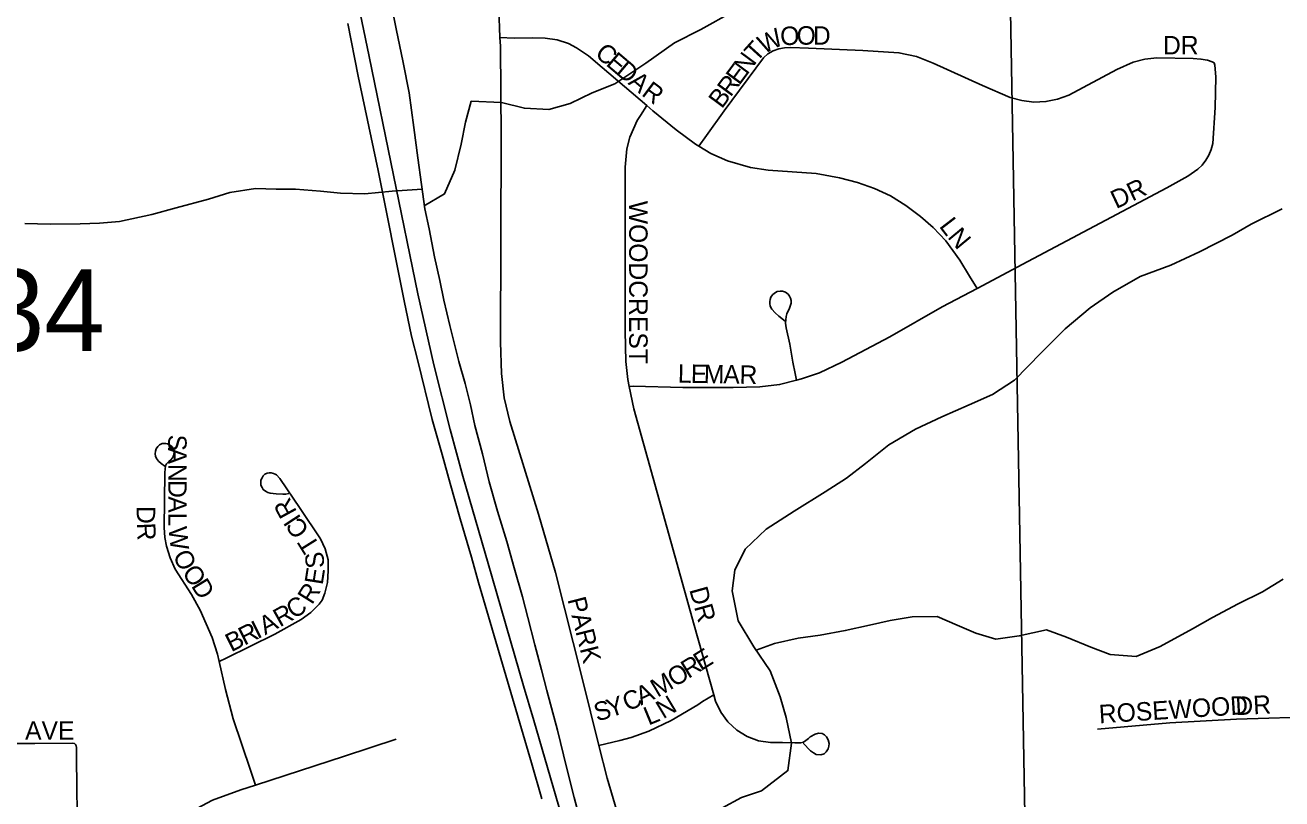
# Model space of a CAD drawing. Extents: x 1985906 to 2360102, y 891258 to 1222054.
# Drawn here: x 2127638 to 2131045, y 1027049 to 1029146 of the extents above; entities that cross this region are included whole.
import ezdxf

# ---------------------------------------------------------------- set-up
doc = ezdxf.new("R2010")
doc.units = 0
for name, color, linetype in [('GM_X_City_Street', 7, 'Continuous'), ('GM_X_City_Street_Text', 7, 'Continuous'), ('GM_X_Minor_River', 7, 'Continuous'), ('GM_X_Section', 7, 'Continuous'), ('GM_X_Section_Text', 7, 'Continuous'), ('GM_X_State_Route', 7, 'Continuous')]:
    doc.layers.add(name, color=color, linetype=linetype)

msp = doc.modelspace()

# ---------------------------------------------------------------- linework, layer by layer
at = {"layer": 'GM_X_City_Street'}
for points in [[(2128925.4, 1029111.7), (2128919.2, 1029268.5), (2128910.3, 1029349.7), (2128894.7, 1029429.9), (2128872.7, 1029508.6), (2128822.4, 1029647.2), (2128746.9, 1029846.9), (2128710.7, 1029956.1), (2128670.5, 1030098.5), (2128656.9, 1030147)], [(2128925.4, 1029111.7), (2128963.4, 1029110.6), (2129013.5, 1029111.3), (2129048.2, 1029110), (2129080.2, 1029106.2), (2129111, 1029095.7), (2129133.1, 1029084.2), (2129165.5, 1029062.7), (2129202.6, 1029030.6), (2129323.1, 1028927.7)], [(2129193.5, 1027193.3), (2129147.7, 1027376.3), (2129076, 1027662.8), (2129029.8, 1027820.2), (2128951.7, 1028071.3), (2128937, 1028135.7), (2128929.5, 1028201.4), (2128927, 1028286.4), (2128928.4, 1028842.4), (2128926.4, 1029088.5), (2128925.4, 1029111.7)], [(2129464.6, 1028817.3), (2129485.5, 1028846.8), (2129532.7, 1028913.4), (2129639.6, 1029057.2), (2129651.5, 1029068.1), (2129665.7, 1029076), (2129681, 1029081.5), (2129697, 1029084.5), (2129713.3, 1029085.3), (2129762, 1029082.8), (2129908.8, 1029077.1), (2130006.5, 1029071), (2130054.3, 1029060.7), (2130099.8, 1029042.7), (2130233.6, 1028981.6), (2130308.5, 1028949.3), (2130340.1, 1028941), (2130372.5, 1028937.3), (2130405.1, 1028938.4), (2130437, 1028945), (2130467.7, 1028956.3), (2130597.2, 1029025.8), (2130642, 1029045.5), (2130673.7, 1029053.5), (2130706.1, 1029057), (2130804.5, 1029055.4), (2130825.4, 1029053.8), (2130842.9, 1029050.3), (2130855.7, 1029046.4), (2130860.8, 1029043.7)], [(2130218.7, 1028432.2), (2130356.3, 1028504.7), (2130732.7, 1028704.5), (2130790.2, 1028736.1), (2130816.9, 1028755), (2130828.7, 1028766.4), (2130838.7, 1028779.4), (2130846.7, 1028793.7), (2130853.1, 1028808.8), (2130857.4, 1028824.6), (2130864.3, 1028922.6), (2130865.7, 1029004.6), (2130863.9, 1029027.4), (2130863.1, 1029036.7), (2130860.8, 1029043.7)], [(2129275.7, 1028166.8), (2129271.7, 1028185.7), (2129266.6, 1028234.6), (2129264.3, 1028316.7), (2129264.7, 1028761.1), (2129269.2, 1028810.1), (2129277, 1028841.9), (2129297.6, 1028886.8), (2129306.3, 1028900.7), (2129323.1, 1028927.7)], [(2129323.1, 1028927.7), (2129339.7, 1028913.5), (2129403.2, 1028862.3), (2129455.1, 1028822.9), (2129464.6, 1028817.3)], [(2129464.6, 1028817.3), (2129497.3, 1028798.1), (2129541.8, 1028778), (2129604.4, 1028759.7), (2129652.6, 1028752.7), (2129782.3, 1028743.2), (2129845.3, 1028732.2), (2129894.3, 1028718.9), (2129940.6, 1028702.7), (2129983.7, 1028683.1), (2130025.6, 1028657.1), (2130065.3, 1028627.2), (2130099.6, 1028597.4), (2130133.9, 1028560.8), (2130172.1, 1028508.4), (2130198.2, 1028465.7), (2130218.7, 1028432.2)], [(2129729, 1028183.5), (2129725.5, 1028201.4), (2129719.5, 1028231.9), (2129710.6, 1028280.9), (2129701.4, 1028325.6), (2129699.6, 1028338.2), (2129700, 1028346.8), (2129701, 1028356), (2129703.3, 1028363.1), (2129710.1, 1028378.4), (2129714.2, 1028391.9), (2129714.7, 1028399.2), (2129712.7, 1028405.8), (2129709.7, 1028411.3), (2129706.4, 1028416.4), (2129699.5, 1028421.7), (2129691.2, 1028424.5), (2129684.7, 1028424.5), (2129676.3, 1028423.5), (2129669.2, 1028419.2), (2129664.2, 1028414.9), (2129659.4, 1028408.5), (2129657.7, 1028402.6), (2129656.8, 1028396.4), (2129656.7, 1028391.4), (2129658.1, 1028384), (2129662.4, 1028375.7), (2129671.2, 1028365.6), (2129681.1, 1028357.3), (2129698, 1028343.9)], [(2129729, 1028183.5), (2129743, 1028187), (2129791.6, 1028203.7), (2129852.3, 1028232.1), (2129981.9, 1028300.9), (2130124.1, 1028382.4), (2130218.7, 1028432.2)], [(2129275.7, 1028166.8), (2129286.3, 1028166.9), (2129421.3, 1028163.7), (2129557, 1028163.7), (2129629.4, 1028165.2), (2129683.1, 1028171.4), (2129729, 1028183.5)], [(2129504.8, 1027330.7), (2129451.4, 1027519.7), (2129288.5, 1028105.5), (2129275.7, 1028166.8)], [(2128164.1, 1027421.2), (2128159.8, 1027440.7), (2128144.9, 1027486.6), (2128112.4, 1027560.5), (2128089.4, 1027603), (2128045.1, 1027671.7), (2128031, 1027702), (2128021.5, 1027733.5), (2128016.9, 1027757.1), (2128014.8, 1027784.5), (2128016.8, 1027931.8), (2128017.5, 1027944), (2128018.3, 1027949.2), (2128019.8, 1027953.4), (2128021.7, 1027956.5), (2128027.6, 1027963.4), (2128033.5, 1027968.1), (2128037.6, 1027973.1), (2128039.9, 1027977), (2128041.4, 1027981.2), (2128042.2, 1027989.1), (2128041.2, 1027994.6), (2128039.2, 1027999.2), (2128035.7, 1028004.2), (2128029.8, 1028008.7), (2128024.2, 1028011.3), (2128019, 1028012.3), (2128014.4, 1028012.3), (2128010, 1028011.7), (2128006.3, 1028010.1), (2128002.6, 1028008), (2127997.7, 1028003.4), (2127993.7, 1027997.9), (2127991.4, 1027991.4), (2127991.1, 1027984.1), (2127992, 1027977.4), (2127994.5, 1027971.4), (2127999.5, 1027964.2), (2128006.6, 1027958.1), (2128017.2, 1027950.8)], [(2128164.1, 1027421.2), (2128183.5, 1027430.6), (2128315.2, 1027494.9), (2128386.6, 1027535), (2128412.7, 1027553.7), (2128435, 1027576.5), (2128443, 1027587.5), (2128450.8, 1027606.4), (2128457.6, 1027635.1), (2128459.7, 1027667), (2128459.2, 1027697.1), (2128451.5, 1027726.5), (2128438.7, 1027754), (2128383.4, 1027835.5), (2128328.7, 1027917.1), (2128319.4, 1027927), (2128315.9, 1027929), (2128311.4, 1027930.9), (2128305.5, 1027932.1), (2128299.5, 1027932.2), (2128294.5, 1027931.5), (2128288.4, 1027928.8), (2128283.4, 1027924.3), (2128280.4, 1027918.9), (2128277.5, 1027912.6), (2128276.9, 1027906), (2128277.4, 1027899), (2128280.3, 1027892.5), (2128283.4, 1027886.9), (2128289.4, 1027882.4), (2128296.1, 1027879.1), (2128302.8, 1027877.5), (2128318.4, 1027875.5), (2128337.1, 1027874.5), (2128344.8, 1027875.1), (2128352.7, 1027876.8)], [(2128262.8, 1027086.2), (2128249.1, 1027126.6), (2128201.8, 1027266), (2128180.9, 1027345.3), (2128164.1, 1027421.2)], [(2129193.5, 1027193.3), (2129250.4, 1027207.3), (2129281, 1027215.3), (2129328.5, 1027232.4), (2129389.2, 1027261.5), (2129461.3, 1027303.9), (2129474.7, 1027313.1), (2129504.8, 1027330.7)], [(2129746.9, 1027199.8), (2129766.8, 1027178.9), (2129774.8, 1027173.6), (2129782.8, 1027169.4), (2129795.4, 1027168.3), (2129804.2, 1027171.3), (2129809.8, 1027176.8), (2129815, 1027184.3), (2129816.8, 1027191.9), (2129817.6, 1027199.2), (2129814.9, 1027208.7), (2129810.7, 1027217.1), (2129804.6, 1027222.1), (2129798.9, 1027225.9), (2129788.6, 1027227.4), (2129779.8, 1027224.7), (2129766.3, 1027216.9), (2129761.7, 1027212.8), (2129754.6, 1027206.8), (2129747.7, 1027202.6), (2129740.2, 1027200.5), (2129724.3, 1027200.5), (2129691.3, 1027201.3), (2129658.4, 1027201.6), (2129625.9, 1027206.4), (2129595, 1027217.6), (2129567.3, 1027235.2), (2129543.4, 1027257.9), (2129523.8, 1027284.2), (2129509.9, 1027314), (2129504.8, 1027330.7)], [(2130544.8, 1027237.7), (2130741.5, 1027254.8), (2130922.2, 1027264.6), (2131155.4, 1027272.2)], [(2126496.1, 1027200), (2126503.7, 1027200.2), (2126533.9, 1027200.9), (2126551.9, 1027201), (2126579.9, 1027200.8), (2126631.9, 1027200.3), (2126730.1, 1027201.2), (2126814.8, 1027200.4), (2127069, 1027200.4), (2127112, 1027200), (2127322.3, 1027198.8), (2127388.3, 1027198.3), (2127551.7, 1027199.4), (2127664.6, 1027199.2), (2127766.1, 1027199.5), (2127772, 1027199.1)], [(2127783.4, 1026855.3), (2127781.9, 1026887.2), (2127780.8, 1026936.8), (2127779.4, 1027003.2), (2127778.3, 1027088), (2127777.8, 1027154.3), (2127777.6, 1027184), (2127777.6, 1027188.5), (2127776.6, 1027192.7), (2127774.9, 1027196.4), (2127772, 1027199.1)], [(2128262.8, 1027086.2), (2128503.7, 1027164.3), (2128644, 1027210.7)], [(2129616.5, 1026222.3), (2129506.9, 1026444.7), (2129315.7, 1026826.7), (2129275.9, 1026917.2), (2129248.2, 1026994.8), (2129215.6, 1027105.3), (2129193.5, 1027193.3)], [(2127913.2, 1026872.9), (2127940.4, 1026886.5), (2127967.9, 1026905.6), (2128015.5, 1026951.3), (2128063.7, 1026994.9), (2128103.4, 1027022.9), (2128146.3, 1027045.3), (2128222.9, 1027073.3), (2128262.8, 1027086.2)]]:
    msp.add_lwpolyline(points, dxfattribs=at)
at = {"layer": 'GM_X_Minor_River'}
for points in [[(2128662.7, 1029044), (2128644, 1029136), (2128627.5, 1029217.9)], [(2128720.3, 1028656.1), (2128775.1, 1028688.4), (2128802.7, 1028752.7), (2128820.2, 1028822.9), (2128831.8, 1028883.1), (2128847.4, 1028939.3), (2128929.4, 1028935.9), (2128991.5, 1028920.3), (2129057.5, 1028916.8), (2129115.4, 1028933.3), (2129175.2, 1028961.8), (2129237, 1028986.2), (2129320.6, 1029042.9), (2129398.2, 1029097.6), (2129469.9, 1029134.2), (2129557.6, 1029182.9)], [(2129150.9, 1026961.2), (2129126.3, 1027053.1), (2129105.7, 1027135), (2129081, 1027235), (2129052.3, 1027342.9), (2129037.9, 1027398.8), (2129019.5, 1027466.8), (2129001, 1027540.8), (2128986.6, 1027596.7), (2128964, 1027674.6), (2128943.6, 1027746.6), (2128919, 1027828.5), (2128896.4, 1027908.4), (2128877.9, 1027984.3), (2128857.4, 1028060.3), (2128845, 1028116.3), (2128830.6, 1028174.2), (2128814.2, 1028234.2), (2128789.6, 1028332.1), (2128773.1, 1028400.1), (2128762.7, 1028454), (2128748.3, 1028518), (2128733.8, 1028594), (2128721.4, 1028648), (2128712.9, 1028714), (2128702.4, 1028786), (2128691.9, 1028868), (2128679.2, 1028962), (2128662.7, 1029044)], [(2128714.6, 1028701.2), (2128633.1, 1028695.4), (2128559.1, 1028688.8), (2128493.1, 1028690.3), (2128439.1, 1028695.9), (2128371.1, 1028701.4), (2128319.1, 1028701), (2128263.1, 1028702.6), (2128193.2, 1028692.1), (2128135.3, 1028673.6), (2128047.5, 1028650.9), (2127981.6, 1028632.4), (2127893.7, 1028613.7), (2127839.8, 1028609.3), (2127787.8, 1028606.9), (2127705.8, 1028606.3), (2127637.8, 1028607.8)], [(2129526.4, 1027024.1), (2129580.2, 1027052.5), (2129634.1, 1027070.9), (2129705.7, 1027125.5), (2129715.2, 1027199.7), (2129700.7, 1027269.7), (2129684.4, 1027325.6), (2129657.9, 1027395.5), (2129613.4, 1027461.2), (2129570.9, 1027531), (2129554.4, 1027613), (2129562, 1027669.1), (2129589.6, 1027725.4), (2129647.2, 1027779.9), (2129722.9, 1027828.5), (2129806.5, 1027881.2), (2129864.3, 1027917.7), (2129916, 1027958.1), (2129979.6, 1028008.7), (2130051.3, 1028051.2), (2130123.1, 1028083.8), (2130196.8, 1028116.4), (2130260.6, 1028144.9), (2130320.4, 1028183.4), (2130391.9, 1028258), (2130457.4, 1028322.6), (2130525, 1028379.2), (2130586.7, 1028421.7), (2130660.4, 1028464.3), (2130744.2, 1028495), (2130821.9, 1028531.6), (2130909.6, 1028576.3), (2130961.4, 1028606.7), (2131045.1, 1028647.4)], [(2129619.9, 1027451.6), (2129669.4, 1027469.7), (2129733.3, 1027484.2), (2129793.2, 1027492.6), (2129861.1, 1027505.2), (2129927, 1027519.7), (2129982.9, 1027532.1), (2130042.8, 1027542.6), (2130110.8, 1027543.1), (2130165, 1027519.5), (2130215.1, 1027497.8), (2130269.2, 1027482.2), (2130333.1, 1027490.7), (2130407, 1027507.3), (2130461.1, 1027487.6), (2130527.3, 1027460.1), (2130579.4, 1027440.5), (2130649.5, 1027435), (2130715.3, 1027461.5), (2130802.9, 1027510.2), (2130856.7, 1027540.7), (2130926.5, 1027577.2), (2130992.2, 1027609.8), (2131048, 1027644.2)]]:
    msp.add_lwpolyline(points, dxfattribs=at)
at = {"layer": 'GM_X_Section'}
for points in [[(2135499.1, 1030852.6), (2135642.2, 1025550.2), (2130421.3, 1025489.7), (2130375.3, 1025487.4), (2130280.1, 1030804)], [(2130280.1, 1030804), (2130375.3, 1025487.4), (2125102, 1025486.6), (2125066.6, 1030831.6)]]:
    msp.add_lwpolyline(points, close=True, dxfattribs=at)
at = {"layer": 'GM_X_State_Route'}
for points in [[(2129579.9, 1025373.6), (2129548.3, 1025474), (2129548.3, 1025474.1), (2129538.9, 1025504.2), (2129506, 1025608.4), (2129423.4, 1025875), (2129324.9, 1026205.3), (2129141.1, 1026835.6), (2129076.9, 1027056.2), (2129016.9, 1027261), (2128989.5, 1027355.6), (2128893.2, 1027686.9), (2128825, 1027923.1), (2128790.3, 1028049.8), (2128746.4, 1028225), (2128702.6, 1028417.1), (2128570.6, 1029060.3), (2128487.6, 1029462.1), (2128441.5, 1029670.3), (2128406.4, 1029813.7), (2128394.3, 1029859.1)], [(2129038.6, 1027048.9), (2129010.4, 1027146.5), (2128866.8, 1027635.4), (2128847.7, 1027703.6), (2128817.8, 1027808.2), (2128790, 1027903.8), (2128768.3, 1027982.4), (2128741.9, 1028077.4), (2128702.8, 1028236.4), (2128685.9, 1028302.8), (2128665.5, 1028398.3), (2128595.4, 1028751.6), (2128541.1, 1029007.5), (2128512.9, 1029149.9)]]:
    msp.add_lwpolyline(points, dxfattribs=at)

# ---------------------------------------------------------------- texts
at = {"layer": 'GM_X_City_Street_Text'}
for s, rotation, p in [('W', 26.4523, (2129640.1, 1029066.5)), ('O', 2.7554, (2129686.1, 1029090.6)), ('O', 0, (2129729.4, 1029092.7)), ('D', 0, (2129773.4, 1029092.7)), ('T', 47.8219, (2129620.4, 1029043.4)), ('DR', 0, (2130722.5, 1029066.3)), ('C', 319.7437, (2129179.9, 1029064)), ('E', 319.7429, (2129210.1, 1029038.4)), ('N', 53.4536, (2129595, 1029009)), ('D', 319.7566, (2129236.9, 1029015.7)), ('E', 53.4448, (2129574, 1028980.7)), ('A', 319.7495, (2129270.5, 1028987.3)), ('R', 53.4263, (2129550.4, 1028948.9)), ('R', 323.1646, (2129306.7, 1028956.8)), ('B', 53.4458, (2129526.8, 1028917.1)), ('DR', 25.1968, (2130595.6, 1028646.8)), ('WOODCREST', 270, (2129275.5, 1028669.7)), ('L', 307.4653, (2130114.1, 1028600.4)), ('N', 309.5754, (2130136.7, 1028570.9)), ('L', 358.9619, (2129407.1, 1028176.9)), ('E', 358.9619, (2129442.3, 1028176.2)), ('M', 358.9815, (2129477.5, 1028175.6)), ('A', 358.9508, (2129530.3, 1028174.7)), ('R', 358.9843, (2129574.3, 1028173.8)), ('S', 270.0547, (2128025.9, 1028036.1)), ('A', 270.0829, (2128025.9, 1028000.8)), ('N', 270.0656, (2128026, 1027956.8)), ('D', 270.0604, (2128026.1, 1027912.9)), ('A', 270.0604, (2128026.1, 1027868.9)), ('R', 118.5969, (2128376.1, 1027827.1)), ('D', 270.1312, (2127940.8, 1027842.5)), ('L', 270.059, (2128026.2, 1027824.9)), ('I', 123.4234, (2128387.7, 1027809.6)), ('R', 272.5152, (2127941, 1027796.2)), ('W', 276.2327, (2128026.5, 1027783.8)), ('C', 125.4615, (2128410.4, 1027777.8)), ('T', 122.0348, (2128438.6, 1027734.4)), ('O', 295.0845, (2128037.6, 1027709.7)), ('S', 96.1962, (2128450.4, 1027676.3)), ('O', 306.1927, (2128061.6, 1027660.8)), ('E', 80.9545, (2128444.5, 1027627.1)), ('D', 301.5316, (2128087, 1027626.2)), ('R', 58.0156, (2128415.9, 1027573.1)), ('DR', 285.5276, (2129438, 1027616.2)), ('R', 29.25, (2128328.7, 1027513.2)), ('C', 33.5071, (2128366.7, 1027534.7)), ('PARK', 284.0405, (2129108, 1027589.6)), ('A', 27.9178, (2128288.7, 1027492)), ('B', 26.5868, (2128197.1, 1027446.1)), ('R', 26.5869, (2128232.5, 1027463.8)), ('I', 26.5846, (2128267.9, 1027481.6)), ('E', 31.8584, (2129469.7, 1027394.5)), ('O', 31.869, (2129398.7, 1027350.3)), ('R', 31.8612, (2129436, 1027373.6)), ('M', 30.6445, (2129352.3, 1027322.8)), ('C', 25.3782, (2129271.9, 1027284.8)), ('A', 24.9324, (2129307.5, 1027301.7)), ('S', 16.4951, (2129188.4, 1027258.2)), ('Y', 18.0211, (2129223.5, 1027268.6)), ('N', 30.9385, (2129367.7, 1027264.4)), ('ROSEWOOD', 3.6209, (2130550.3, 1027253.5)), ('DR', 3.0167, (2130920, 1027275.5)), ('L', 22.4076, (2129328, 1027247.4)), ('AVE', 0, (2127638.1, 1027209.5))]:
    msp.add_text(s, height=50, rotation=rotation, dxfattribs=at).set_placement(p)
at = {"layer": 'GM_X_Section_Text'}
msp.add_text('34', height=221, rotation=0, dxfattribs=at).set_placement((2127525.9, 1028263))

doc.saveas('drawing.dxf')
